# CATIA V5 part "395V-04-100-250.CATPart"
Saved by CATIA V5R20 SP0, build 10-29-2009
Part number: 395V-04-100-250
Source: Unknown
Property "A": "50.000"
Property "ARTICLENO": "395V-04-100-250"
Property "BOMINFO": "395V-04-100-250"
Property "CODE": "395V-04-100-250"
Property "D": "80.000"
Property "D1": "27.000"
Property "D2": "39.000"
Property "D3": "110.000"
Property "FORM": "B"
Property "L": "250.000"
Property "L1": "25.000"
Property "L2": "100.000"
Property "L3": "65.000"
Property "L4": "15.000"
Property "LINA": "395V-04-100-250"
Property "MAXLOAD": "12500 Kg"
Property "MDW": "25000 Kg"
Property "NB": "395V-04-100-250"
Property "NBSYN": "$CODE."
Property "NN": "395V"
Property "NT": "VDI 3366 Lifting Brackets"
Property "SUPPLIER": "CF"
Property "T": "25.500"
Property "W": "100.000"
Bounding box of the stored display mesh (mm): x -50.01 to 50.01, y 0 to 250, z -50 to 50
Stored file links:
  C:\Users\Utente\Desktop\3D files 395V\395V-04-100-250.CATPart
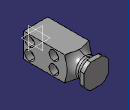
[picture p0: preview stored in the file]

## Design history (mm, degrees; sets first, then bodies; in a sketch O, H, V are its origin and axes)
Body1 "Geometry.1" (main body)
  Solid1 "395V-04-100-250.catpart": solid without history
